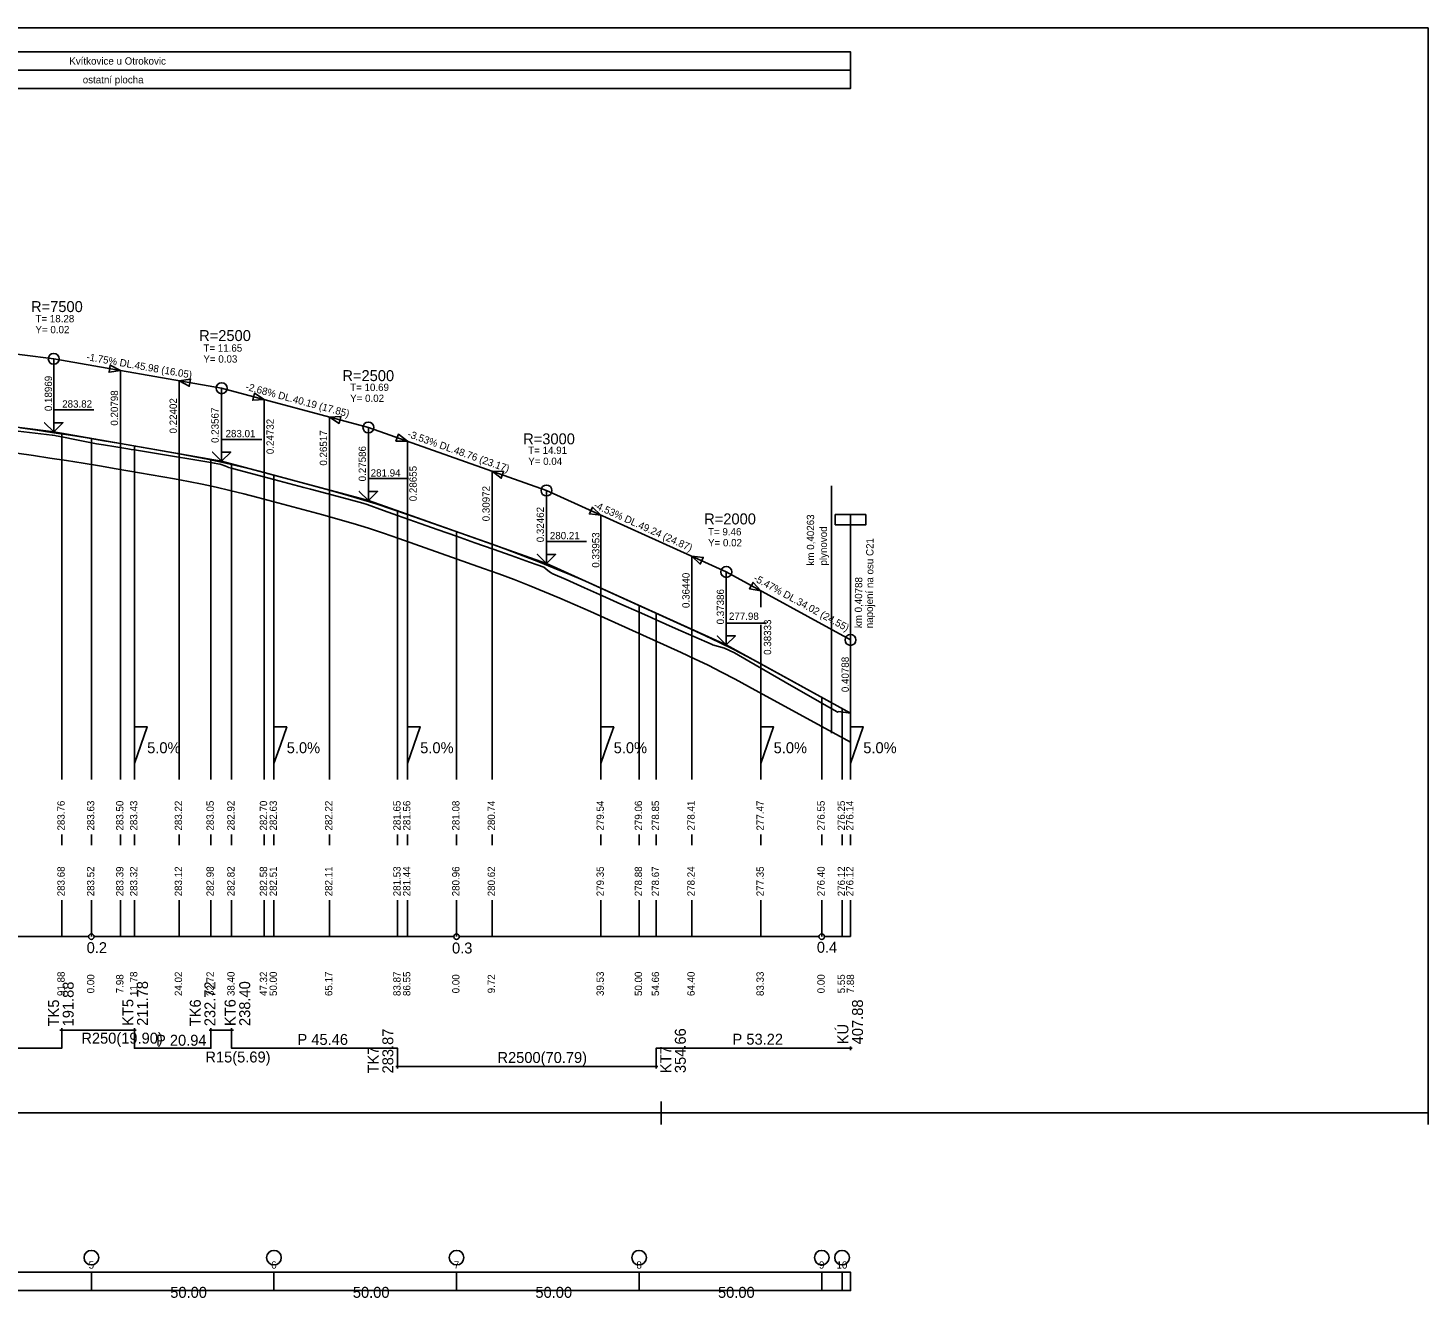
# Model space of a CAD drawing. Extents: x 612.5 to 675.5, y 110.4 to 145.2.
# Drawn here: x 637.12 to 675.46, y 110.45 to 145.21 of the extents above; entities that cross this region are included whole.
import ezdxf

# ---------------------------------------------------------------- set-up
doc = ezdxf.new("R2010")
doc.units = 0
for name, color, linetype in [('KOTA', 7, 'Continuous'), ('NOVY_STAV', 7, 'Continuous'), ('NS_OBLOUK', 7, 'Continuous'), ('REZY_PO', 7, 'Continuous'), ('SESTAVY_REZU_PO', 7, 'Continuous'), ('SKLONOVE_POMERY', 7, 'Continuous'), ('SMEROVE_POMERY', 7, 'Continuous'), ('SMEROVE_POMERY_KOD', 7, 'Continuous'), ('SVK_STAT', 7, 'Continuous'), ('TABULKY', 7, 'Continuous'), ('u_drenaz', 7, 'Continuous'), ('u_popis', 7, 'Continuous'), ('u_pricne_rezy', 7, 'Continuous'), ('x_formát_rám', 7, 'Continuous')]:
    doc.layers.add(name, color=color, linetype=linetype)

msp = doc.modelspace()

# ---------------------------------------------------------------- linework, layer by layer
at = {"layer": 'KOTA'}
for points in [[(637.829, 134.158), (637.579, 134.408), (637.829, 134.158), (637.829, 134.758), (638.929, 134.758)], [(637.829, 134.408), (637.829, 134.158), (638.079, 134.408), (637.829, 134.408)], [(637.829, 134.158), (638.079, 134.408), (637.829, 134.408)], [(637.829, 134.158), (637.829, 134.158)], [(642.428, 133.354), (642.178, 133.604), (642.428, 133.354), (642.428, 133.954), (643.528, 133.954)], [(642.428, 133.604), (642.428, 133.354), (642.678, 133.604), (642.428, 133.604)], [(642.428, 133.354), (642.678, 133.604), (642.428, 133.604)], [(642.428, 133.354), (642.428, 133.354)], [(646.446, 132.278), (646.196, 132.528), (646.446, 132.278), (646.446, 132.878), (647.546, 132.878)], [(646.446, 132.528), (646.446, 132.278), (646.696, 132.528), (646.446, 132.528)], [(646.446, 132.278), (646.696, 132.528), (646.446, 132.528)], [(646.446, 132.278), (646.446, 132.278)], [(651.323, 130.554), (651.073, 130.804), (651.323, 130.554), (651.323, 131.154), (652.423, 131.154)], [(651.323, 130.804), (651.323, 130.554), (651.573, 130.804), (651.323, 130.804)], [(651.323, 130.554), (651.573, 130.804), (651.323, 130.804)], [(651.323, 130.554), (651.323, 130.554)], [(656.247, 128.325), (655.997, 128.575), (656.247, 128.325), (656.247, 128.925), (657.347, 128.925)], [(656.247, 128.575), (656.247, 128.325), (656.497, 128.575), (656.247, 128.575)], [(656.247, 128.325), (656.497, 128.575), (656.247, 128.575)], [(656.247, 128.325), (656.247, 128.325)]]:
    msp.add_lwpolyline(points, dxfattribs=at)
at = {"layer": 'NOVY_STAV'}
msp.add_line((659.648, 128.463), (659.648, 131.615), dxfattribs=at)
for points in [[(618.86, 138.641), (619.971, 138.487), (623.923, 136.231), (627.343, 136.08), (630.022, 135.141), (637.829, 134.158), (642.428, 133.354), (646.446, 132.278), (651.323, 130.554), (656.247, 128.325), (659.648, 126.463)], [(630.022, 137.141), (637.829, 136.158)], [(637.829, 134.158), (637.829, 136.158)], [(637.829, 136.158), (642.428, 135.354)], [(642.428, 133.354), (642.428, 135.354)], [(642.428, 135.354), (646.446, 134.278)], [(636.915, 134.267), (637.372, 134.203), (637.829, 134.135), (638.287, 134.065), (638.744, 133.992), (639.201, 133.917), (639.658, 133.838), (641.263, 133.558), (641.651, 133.487), (642.039, 133.41), (642.428, 133.327), (642.816, 133.238), (643.204, 133.143), (643.593, 133.042), (645.378, 132.564), (645.805, 132.446), (646.233, 132.32), (646.66, 132.187), (647.088, 132.047), (647.515, 131.9), (649.832, 131.081), (650.258, 130.927), (650.684, 130.768), (651.11, 130.602), (651.536, 130.431), (651.961, 130.253), (652.387, 130.069), (652.813, 129.879), (655.3, 128.753), (655.679, 128.578), (656.057, 128.396), (656.436, 128.207), (656.815, 128.01), (657.193, 127.807), (659.648, 126.463)], [(646.446, 132.278), (646.446, 134.278)], [(646.446, 134.278), (651.323, 132.554)], [(651.323, 130.554), (651.323, 132.554)], [(651.323, 132.554), (656.247, 130.325)], [(656.247, 128.325), (656.247, 130.325)], [(656.247, 130.325), (659.648, 128.463)], [(659.648, 126.463), (659.648, 128.463)]]:
    msp.add_lwpolyline(points, dxfattribs=at)
for points in [[(659.228, 131.895), (659.648, 131.895), (659.648, 131.615), (659.228, 131.615)], [(660.068, 131.895), (659.648, 131.895), (659.648, 131.615), (660.068, 131.615)]]:
    msp.add_lwpolyline(points, close=True, dxfattribs=at)
for centre in [(637.829, 136.158), (642.428, 135.354), (646.446, 134.278), (651.323, 132.554), (656.247, 130.325), (659.648, 128.463)]:
    msp.add_circle(centre, 0.15, dxfattribs=at)
at = {"layer": 'NS_OBLOUK'}
for points in [[(639.345, 135.791), (639.658, 135.838), (639.379, 135.988), (639.345, 135.791)], [(639.658, 133.838), (639.658, 135.838)], [(641.263, 135.558), (641.541, 135.408), (641.575, 135.605), (641.263, 135.558)], [(641.263, 133.558), (641.263, 135.558)], [(643.277, 135.023), (643.593, 135.042), (643.329, 135.216), (643.277, 135.023)], [(643.593, 133.042), (643.593, 135.042)], [(645.378, 134.564), (645.642, 134.39), (645.693, 134.583), (645.378, 134.564)], [(645.378, 132.564), (645.378, 134.564)], [(647.199, 133.905), (647.515, 133.9), (647.266, 134.094), (647.199, 133.905)], [(647.515, 131.9), (647.515, 133.9)], [(649.832, 131.081), (649.832, 133.081)], [(649.832, 133.081), (650.082, 132.887), (650.148, 133.075), (649.832, 133.081)], [(652.499, 131.912), (652.813, 131.879), (652.581, 132.094), (652.499, 131.912)], [(652.813, 129.879), (652.813, 131.879)], [(655.3, 128.753), (655.3, 130.753)], [(655.3, 130.753), (655.532, 130.538), (655.615, 130.72), (655.3, 130.753)], [(656.882, 129.863), (657.193, 129.807), (656.978, 130.038), (656.882, 129.863)], [(657.193, 129.356), (657.193, 129.807)], [(657.193, 127.807), (657.193, 128.874)]]:
    msp.add_lwpolyline(points, dxfattribs=at)
for points in [[(639.658, 135.838), (639.379, 135.988), (639.345, 135.791)], [(641.263, 135.558), (641.575, 135.605), (641.541, 135.408)], [(643.593, 135.042), (643.329, 135.216), (643.277, 135.023)], [(645.378, 134.564), (645.693, 134.583), (645.642, 134.39)], [(647.515, 133.9), (647.266, 134.094), (647.199, 133.905)], [(649.832, 133.081), (650.148, 133.075), (650.082, 132.887)], [(652.813, 131.879), (652.581, 132.094), (652.499, 131.912)], [(655.3, 130.753), (655.615, 130.72), (655.532, 130.538)], [(657.193, 129.807), (656.978, 130.038), (656.882, 129.863)]]:
    msp.add_lwpolyline(points, close=True, dxfattribs=at)
at = {"layer": 'REZY_PO'}
msp.add_lwpolyline([(636.86, 134.179), (637.787, 134.069), (637.86, 134.055), (637.892, 134.049), (638.049, 134.019), (638.454, 133.94), (638.86, 133.86), (638.86, 133.86), (638.86, 133.86), (639.005, 133.831), (639.194, 133.802), (639.527, 133.748), (639.86, 133.694), (639.949, 133.68), (640.038, 133.665), (640.86, 133.53), (641.86, 133.366), (642.132, 133.321), (642.132, 133.321), (642.132, 133.321), (642.227, 133.305), (642.322, 133.288), (642.385, 133.276), (642.416, 133.265), (642.511, 133.228), (642.606, 133.19), (642.617, 133.186), (642.701, 133.164), (642.701, 133.164), (642.701, 133.164), (642.86, 133.122), (643.86, 132.855), (644.676, 132.637), (644.86, 132.588), (645.86, 132.322), (646.295, 132.206), (646.408, 132.169), (646.86, 132.009), (647.247, 131.872), (647.247, 131.872), (647.247, 131.872), (647.554, 131.763), (647.86, 131.654), (648.36, 131.478), (648.86, 131.301), (649.36, 131.124), (649.86, 130.948), (650.36, 130.772), (650.86, 130.596), (651.071, 130.522), (651.254, 130.451), (651.36, 130.366), (651.431, 130.309), (651.498, 130.277), (651.86, 130.115), (652.36, 129.891), (652.86, 129.667), (653.36, 129.444), (653.86, 129.222), (653.86, 129.222), (653.86, 129.222), (654.093, 129.119), (654.326, 129.015), (654.326, 129.015), (654.326, 129.015), (654.86, 128.778), (655.86, 128.335), (655.872, 128.33), (656.196, 128.239), (656.473, 128.106), (656.86, 127.884), (657.86, 127.31), (658.86, 126.736), (659.286, 126.492), (659.299, 126.482), (659.32, 126.5), (659.648, 126.463)], dxfattribs=at)
at = {"layer": 'SESTAVY_REZU_PO'}
for points in [[(628.935, 120.341), (638.785, 120.341)], [(638.935, 120.341), (648.785, 120.341)], [(648.935, 120.341), (658.785, 120.341)], [(658.935, 120.341), (659.648, 120.341)]]:
    msp.add_lwpolyline(points, dxfattribs=at)
for centre in [(638.86, 120.341), (648.86, 120.341), (658.86, 120.341)]:
    msp.add_circle(centre, 0.075, dxfattribs=at)
at = {"layer": 'SMEROVE_POMERY'}
for points in [[(640.038, 126.081), (640.038, 125.081), (640.038, 125.081), (640.213, 125.581), (640.388, 126.081), (640.038, 126.081)], [(643.86, 126.081), (643.86, 125.081), (643.86, 125.081), (644.035, 125.581), (644.21, 126.081), (643.86, 126.081)], [(647.515, 126.081), (647.515, 125.081), (647.515, 125.081), (647.69, 125.581), (647.865, 126.081), (647.515, 126.081)], [(652.813, 126.081), (652.813, 125.081), (652.813, 125.081), (652.988, 125.581), (653.163, 126.081), (652.813, 126.081)], [(657.193, 126.081), (657.193, 125.081), (657.193, 125.081), (657.368, 125.581), (657.543, 126.081), (657.193, 126.081)], [(659.648, 126.081), (659.648, 125.081), (659.648, 125.081), (659.823, 125.581), (659.998, 126.081), (659.648, 126.081)], [(633.346, 117.284), (638.049, 117.284), (638.049, 117.784), (640.038, 117.784), (640.038, 117.284), (642.132, 117.284), (642.132, 117.784), (642.701, 117.784), (642.701, 117.284), (647.247, 117.284), (647.247, 116.784), (654.326, 116.784), (654.326, 117.284), (659.648, 117.284)]]:
    msp.add_lwpolyline(points, dxfattribs=at)
at = {"layer": 'SMEROVE_POMERY_KOD'}
for points in [[(637.999, 117.784), (638.099, 117.784)], [(638.049, 117.734), (638.049, 117.834)], [(639.988, 117.784), (640.088, 117.784)], [(640.038, 117.734), (640.038, 117.834)], [(642.082, 117.784), (642.182, 117.784)], [(642.132, 117.734), (642.132, 117.834)], [(642.651, 117.784), (642.751, 117.784)], [(642.701, 117.734), (642.701, 117.834)], [(659.648, 117.234), (659.648, 117.334)], [(659.598, 117.284), (659.698, 117.284)], [(647.197, 116.784), (647.297, 116.784)], [(647.247, 116.734), (647.247, 116.834)], [(654.276, 116.784), (654.376, 116.784)], [(654.326, 116.734), (654.326, 116.834)]]:
    msp.add_lwpolyline(points, dxfattribs=at)
at = {"layer": 'SVK_STAT'}
for points in [[(638.049, 124.641), (638.049, 134.119)], [(638.86, 124.641), (638.86, 133.977)], [(639.658, 124.641), (639.658, 133.838)], [(640.038, 124.641), (640.038, 133.772)], [(641.263, 124.641), (641.263, 133.558)], [(642.132, 124.641), (642.132, 133.406)], [(642.701, 124.641), (642.701, 133.281)], [(643.593, 124.641), (643.593, 133.042)], [(643.86, 124.641), (643.86, 132.97)], [(645.378, 124.641), (645.378, 132.564)], [(647.247, 124.641), (647.247, 131.995)], [(647.515, 124.641), (647.515, 131.9)], [(648.86, 124.641), (648.86, 131.424)], [(649.832, 124.641), (649.832, 131.081)], [(652.813, 124.641), (652.813, 129.879)], [(653.86, 124.641), (653.86, 129.405)], [(654.326, 124.641), (654.326, 129.194)], [(655.3, 124.641), (655.3, 128.753)], [(657.193, 124.641), (657.193, 127.807)], [(658.86, 124.641), (658.86, 126.894)], [(659.416, 124.641), (659.416, 126.59)], [(659.648, 124.641), (659.648, 126.463)], [(638.049, 122.841), (638.049, 123.141)], [(638.86, 122.841), (638.86, 123.141)], [(639.658, 122.841), (639.658, 123.141)], [(640.038, 122.841), (640.038, 123.141)], [(641.263, 122.841), (641.263, 123.141)], [(642.132, 122.841), (642.132, 123.141)], [(642.701, 122.841), (642.701, 123.141)], [(643.593, 122.841), (643.593, 123.141)], [(643.86, 122.841), (643.86, 123.141)], [(645.378, 122.841), (645.378, 123.141)], [(647.247, 122.841), (647.247, 123.141)], [(647.515, 122.841), (647.515, 123.141)], [(648.86, 122.841), (648.86, 123.141)], [(649.832, 122.841), (649.832, 123.141)], [(652.813, 122.841), (652.813, 123.141)], [(653.86, 122.841), (653.86, 123.141)], [(654.326, 122.841), (654.326, 123.141)], [(655.3, 122.841), (655.3, 123.141)], [(657.193, 122.841), (657.193, 123.141)], [(658.86, 122.841), (658.86, 123.141)], [(659.416, 122.841), (659.416, 123.141)], [(659.648, 122.841), (659.648, 123.141)], [(638.049, 120.341), (638.049, 121.341)], [(638.86, 120.341), (638.86, 121.341)], [(639.658, 120.341), (639.658, 121.341)], [(640.038, 120.341), (640.038, 121.341)], [(641.263, 120.341), (641.263, 121.341)], [(642.132, 120.341), (642.132, 121.341)], [(642.701, 120.341), (642.701, 121.341)], [(643.593, 120.341), (643.593, 121.341)], [(643.86, 120.341), (643.86, 121.341)], [(645.378, 120.341), (645.378, 121.341)], [(647.247, 120.341), (647.247, 121.341)], [(647.515, 120.341), (647.515, 121.341)], [(648.86, 120.341), (648.86, 121.341)], [(649.832, 120.341), (649.832, 121.341)], [(652.813, 120.341), (652.813, 121.341)], [(653.86, 120.341), (653.86, 121.341)], [(654.326, 120.341), (654.326, 121.341)], [(655.3, 120.341), (655.3, 121.341)], [(657.193, 120.341), (657.193, 121.341)], [(658.86, 120.341), (658.86, 121.341)], [(659.416, 120.341), (659.416, 121.341)], [(659.648, 120.341), (659.648, 121.341)]]:
    msp.add_lwpolyline(points, dxfattribs=at)
at = {"layer": 'TABULKY'}
for points in [[(618.86, 143.559), (659.648, 143.559), (659.648, 144.559), (618.86, 144.559), (618.86, 143.559)], [(618.86, 144.059), (659.648, 144.059)]]:
    msp.add_lwpolyline(points, dxfattribs=at)
at = {"layer": 'u_drenaz'}
msp.add_lwpolyline([(636.82, 133.574), (637.272, 133.51), (637.725, 133.443), (638.178, 133.374), (638.631, 133.301), (639.084, 133.226), (639.538, 133.148), (641.14, 132.869), (641.52, 132.799), (641.898, 132.724), (642.276, 132.644), (642.655, 132.557), (643.033, 132.464), (643.414, 132.365), (645.194, 131.888), (645.613, 131.772), (646.03, 131.65), (646.447, 131.52), (646.864, 131.384), (647.284, 131.239), (649.597, 130.422), (650.016, 130.27), (650.434, 130.114), (650.852, 129.951), (651.27, 129.783), (651.688, 129.608), (652.106, 129.428), (652.526, 129.241), (655.009, 128.117), (655.38, 127.945), (655.749, 127.768), (656.118, 127.583), (656.487, 127.391), (656.859, 127.191), (659.648, 125.665)], dxfattribs=at)
at = {"layer": 'u_popis'}
msp.add_lwpolyline([(659.123, 125.911), (659.123, 132.682)], dxfattribs=at)
at = {"layer": 'u_pricne_rezy'}
for points in [[(618.86, 110.654), (659.648, 110.654), (659.648, 111.154), (618.86, 111.154), (618.86, 110.654)], [(638.86, 110.654), (638.86, 111.154)], [(643.86, 110.654), (643.86, 111.154)], [(648.86, 110.654), (648.86, 111.154)], [(653.86, 110.654), (653.86, 111.154)], [(658.86, 110.654), (658.86, 111.154)], [(659.416, 110.654), (659.416, 111.154)]]:
    msp.add_lwpolyline(points, dxfattribs=at)
for centre in [(638.86, 111.554), (643.86, 111.554), (648.86, 111.554), (653.86, 111.554), (658.86, 111.554), (659.416, 111.554)]:
    msp.add_circle(centre, 0.2, dxfattribs=at)
at = {"layer": 'x_formát_rám'}
for p, q in [((654.462, 115.826), (654.462, 115.201)), ((675.462, 115.826), (675.462, 115.201))]:
    msp.add_line(p, q, dxfattribs=at)
msp.add_lwpolyline([(612.462, 115.514), (675.462, 115.514), (675.462, 145.214), (612.462, 145.214)], close=True, dxfattribs=at)

# ---------------------------------------------------------------- texts
at = {"layer": 'KOTA'}
for s, p in [('283.82', (638.061, 134.823)), ('283.01', (642.535, 134.012)), ('281.94', (646.508, 132.935)), ('280.21', (651.415, 131.219)), ('277.98', (656.319, 129.012))]:
    msp.add_text(s, height=0.2, dxfattribs=at).set_placement(p)
at = {"layer": 'NOVY_STAV'}
for s, rotation, p in [('-1.75% DL.45.98 (16.05)', 350.0894, (638.713, 136.122)), (' 0.18969', 90, (637.783, 134.652)), ('-2.68% DL.40.19 (17.85)', 345.0017, (643.067, 135.313)), (' 0.23567', 90, (642.346, 133.781)), ('-3.53% DL.48.76 (23.17)', 340.5358, (647.503, 134.022)), (' 0.27586', 90, (646.379, 132.729)), (' 0.32462', 90, (651.253, 131.062)), ('-4.53% DL.49.24 (24.87)', 335.6398, (652.595, 132.086)), ('napojení na osu C21', 89.5404, (660.26, 128.782)), ('-5.47% DL.34.02 (24.55)', 331.3025, (656.973, 130.094)), ('km 0,40788', 89.5404, (659.96, 128.785)), (' 0.37386', 90, (656.185, 128.814)), (' 0.40788', 90, (659.602, 126.96))]:
    msp.add_text(s, height=0.2, rotation=rotation, dxfattribs=at).set_placement(p)
at = {"layer": 'NS_OBLOUK'}
for s, height, p in [('R=7500', 0.3, (637.208, 137.438)), ('T= 18.28', 0.2, (637.329, 137.158)), ('Y= 0.02', 0.2, (637.329, 136.858)), ('R=2500', 0.3, (641.811, 136.645)), ('T= 11.65', 0.2, (641.928, 136.354)), ('Y= 0.03', 0.2, (641.928, 136.054)), ('R=2500', 0.3, (645.734, 135.548)), ('T= 10.69', 0.2, (645.946, 135.278)), ('Y= 0.02', 0.2, (645.946, 134.978)), ('R=3000', 0.3, (650.684, 133.817)), ('T= 14.91', 0.2, (650.823, 133.554)), ('Y= 0.04', 0.2, (650.823, 133.254)), ('R=2000', 0.3, (655.641, 131.626)), ('T= 9.46', 0.2, (655.747, 131.325)), ('Y= 0.02', 0.2, (655.747, 131.025))]:
    msp.add_text(s, height=height, dxfattribs=at).set_placement(p)
for s, p in [(' 0.20798', (639.591, 134.254)), (' 0.22402', (641.201, 134.04)), (' 0.24732', (643.855, 133.474)), (' 0.26517', (645.314, 133.16)), (' 0.28655', (647.769, 132.185)), (' 0.30972', (649.768, 131.636)), (' 0.33953', (652.772, 130.366)), (' 0.36440', (655.241, 129.262)), (' 0.38333', (657.475, 127.98))]:
    msp.add_text(s, height=0.2, rotation=90, dxfattribs=at).set_placement(p)
at = {"layer": 'SESTAVY_REZU_PO'}
for s, p in [('0.2', (638.731, 119.89)), ('0.3', (648.736, 119.88)), ('0.4', (658.726, 119.9))]:
    msp.add_text(s, height=0.3, dxfattribs=at).set_placement(p)
at = {"layer": 'SKLONOVE_POMERY'}
for p in [(640.388, 125.362), (644.21, 125.362), (647.865, 125.362), (653.163, 125.362), (657.543, 125.362), (659.998, 125.362)]:
    msp.add_text('5.0%', height=0.3, dxfattribs=at).set_placement(p)
at = {"layer": 'SMEROVE_POMERY'}
for s, p in [('R250(19.90)', (638.585, 117.412)), ('P 20.94', (640.631, 117.355)), ('P 45.46', (644.505, 117.377)), ('P 53.22', (656.417, 117.383)), ('R15(5.69)', (641.982, 116.896)), ('R2500(70.79)', (649.98, 116.883))]:
    msp.add_text(s, height=0.3, dxfattribs=at).set_placement(p)
at = {"layer": 'SMEROVE_POMERY_KOD'}
for s, p in [('191.88', (638.375, 117.884)), ('211.78', (640.41, 117.899)), ('232.72', (642.256, 117.889)), ('238.40', (643.209, 117.894)), ('TK5', (637.975, 117.884)), ('KT5', (640.01, 117.899)), ('TK6', (641.856, 117.889)), ('KT6', (642.809, 117.894)), ('407.88', (659.99, 117.394)), ('283.87', (647.128, 116.596)), ('354.66', (655.138, 116.606)), ('KÚ', (659.59, 117.394)), ('KT7', (654.738, 116.606)), ('TK7', (646.728, 116.596))]:
    msp.add_text(s, height=0.3, rotation=90, dxfattribs=at).set_placement(p)
at = {"layer": 'SVK_STAT'}
for s, p in [(' 283.76', (638.129, 123.171)), (' 283.63', (638.94, 123.171)), (' 283.50', (639.738, 123.171)), (' 283.43', (640.118, 123.171)), (' 283.22', (641.343, 123.171)), (' 283.05', (642.212, 123.171)), (' 282.92', (642.781, 123.171)), (' 282.70', (643.673, 123.171)), (' 282.63', (643.94, 123.171)), (' 282.22', (645.458, 123.171)), (' 281.65', (647.327, 123.171)), (' 281.56', (647.595, 123.171)), (' 281.08', (648.94, 123.171)), (' 280.74', (649.912, 123.171)), (' 279.54', (652.893, 123.171)), (' 279.06', (653.94, 123.171)), (' 278.85', (654.406, 123.171)), (' 278.41', (655.38, 123.171)), (' 277.47', (657.273, 123.171)), (' 276.55', (658.94, 123.171)), (' 276.25', (659.496, 123.171)), (' 276.14', (659.728, 123.171)), (' 283.68', (638.129, 121.371)), (' 283.52', (638.94, 121.371)), (' 283.39', (639.738, 121.371)), (' 283.32', (640.118, 121.371)), (' 283.12', (641.343, 121.371)), (' 282.98', (642.212, 121.371)), (' 282.82', (642.781, 121.371)), (' 282.58', (643.673, 121.371)), (' 282.51', (643.94, 121.371)), (' 282.11', (645.458, 121.371)), (' 281.53', (647.327, 121.371)), (' 281.44', (647.595, 121.371)), (' 280.96', (648.94, 121.371)), (' 280.62', (649.912, 121.371)), (' 279.35', (652.893, 121.371)), (' 278.88', (653.94, 121.371)), (' 278.67', (654.406, 121.371)), (' 278.24', (655.38, 121.371)), (' 277.35', (657.273, 121.371)), (' 276.40', (658.94, 121.371)), (' 276.12', (659.496, 121.371)), (' 276.12', (659.728, 121.371)), (' 91.88', (638.129, 118.641)), ('  0.00', (638.94, 118.641)), ('  7.98', (639.738, 118.641)), (' 11.78', (640.118, 118.641)), (' 24.02', (641.343, 118.641)), (' 32.72', (642.212, 118.641)), (' 38.40', (642.781, 118.641)), (' 47.32', (643.673, 118.641)), (' 50.00', (643.94, 118.641)), (' 65.17', (645.458, 118.641)), (' 83.87', (647.327, 118.641)), (' 86.55', (647.595, 118.641)), ('  0.00', (648.94, 118.641)), ('  9.72', (649.912, 118.641)), (' 39.53', (652.893, 118.641)), (' 50.00', (653.94, 118.641)), (' 54.66', (654.406, 118.641)), (' 64.40', (655.38, 118.641)), (' 83.33', (657.273, 118.641)), ('  0.00', (658.94, 118.641)), ('  5.55', (659.496, 118.641)), ('  7.88', (659.746, 118.641))]:
    msp.add_text(s, height=0.2, rotation=90, dxfattribs=at).set_placement(p)
at = {"layer": 'TABULKY'}
for s, p in [('Kvítkovice u Otrokovic', (638.256, 144.211)), ('ostatní plocha', (638.624, 143.698))]:
    msp.add_text(s, height=0.2, dxfattribs=at).set_placement(p)
at = {"layer": 'u_popis'}
for s, p in [('km 0,40263', (658.652, 130.5)), ('plynovod', (659.002, 130.5))]:
    msp.add_text(s, height=0.2, rotation=90, dxfattribs=at).set_placement(p)
at = {"layer": 'u_pricne_rezy'}
for s, height, p in [('5', 0.2, (638.785, 111.254)), ('6', 0.2, (643.785, 111.254)), ('7', 0.2, (648.785, 111.254)), ('8', 0.2, (653.785, 111.254)), ('9', 0.2, (658.785, 111.254)), ('10', 0.2, (659.265, 111.254)), ('50.00', 0.3, (641.02, 110.454)), ('50.00', 0.3, (646.02, 110.454)), ('50.00', 0.3, (651.02, 110.454)), ('50.00', 0.3, (656.02, 110.454))]:
    msp.add_text(s, height=height, dxfattribs=at).set_placement(p)

doc.saveas('drawing.dxf')
